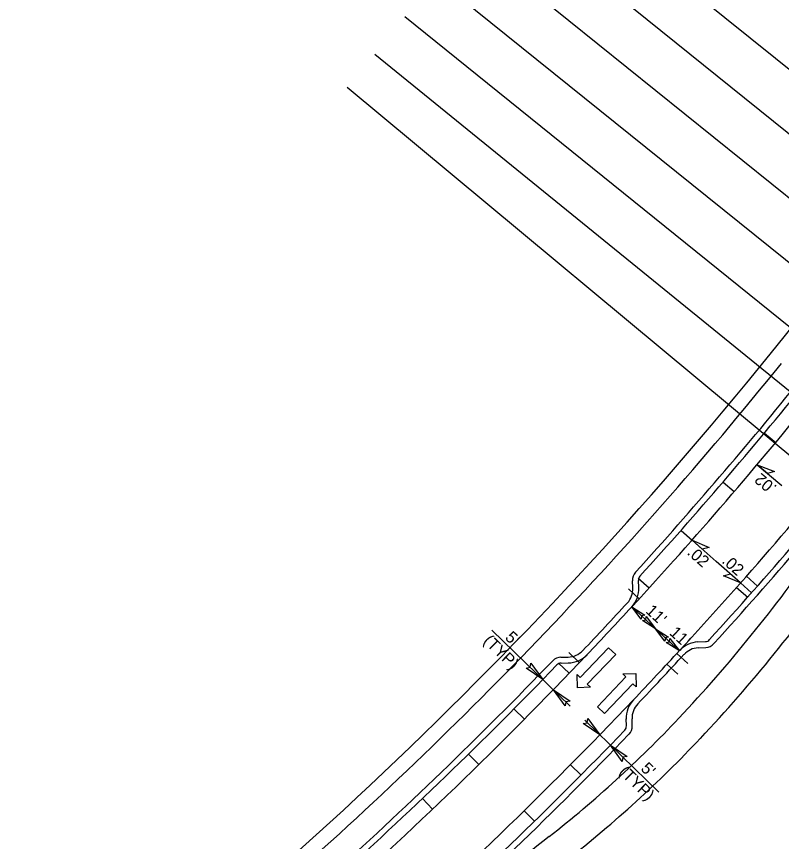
# Model space of a CAD drawing. Extents: x 1486489 to 1490134, y 497089 to 500876.
# Drawn here: x 1488292.7 to 1488552.5, y 498768.1 to 499048.4 of the extents above; entities that cross this region are included whole.
import ezdxf

# ---------------------------------------------------------------- set-up
doc = ezdxf.new("R2010")
doc.units = 0
for name, color, linetype in [('DEV PRELIMINARY STAMP CELL', 7, 'Continuous'), ('Gray Area Fill Shapes', 7, 'Continuous'), ('Prop Horizontal Alignment Station Label', 7, 'Continuous'), ('Scratch_Level_5', 7, 'Continuous'), ('Sheet Block Title CELL', 7, 'Continuous'), ('Sheet Border Standard 30in CELL', 7, 'Continuous'), ('Sheet Cutting Line CELL', 7, 'Continuous'), ('Sheet Plan CELL', 7, 'Continuous'), ('Sheet Plot Border Inside CELL', 7, 'Continuous'), ('Sheet Plot Border Outside CELL', 7, 'Continuous'), ('Sheet Sticker Exception Certification CELL', 7, 'Continuous'), ('Sheet Title CELL', 7, 'Continuous')]:
    doc.layers.add(name, color=color, linetype=linetype)

msp = doc.modelspace()

# ---------------------------------------------------------------- linework, layer by layer
at = {"layer": 'DEV PRELIMINARY STAMP CELL'}
for p, q in [((1488544.22, 498896.09), (1488552.63, 498889)), ((1488522.12, 498870.48), (1488530.36, 498863.19)), ((1488538.61, 498855.91), (1488530.36, 498863.19))]:
    msp.add_line(p, q, dxfattribs=at)
for points in [[(1488544.22, 498896.09), (1488550.1, 498893.75), (1488547.76, 498893.11)], [(1488522.12, 498870.48), (1488527.94, 498868.01), (1488525.58, 498867.42)], [(1488538.61, 498855.91), (1488532.79, 498858.38), (1488535.14, 498858.97)]]:
    msp.add_lwpolyline(points, close=True, dxfattribs=at)
at = {"layer": 'Prop Horizontal Alignment Station Label'}
msp.add_line((1488548.61, 498933.63), (1488574.78, 498966.09), dxfattribs=at)
for centre, radius, start, end in [((1487424.96, 499839.79), 1443.5, 305.25533, 321.11565), ((1487424.96, 499839.79), 1448.5, 311.19416, 321.11565), ((1488157.43, 499149.47), 495, 316.6966, 325.3537), ((1488157.43, 499149.47), 505, 316.6966, 325.3537), ((1488230.2, 499080.88), 395, 308.0345, 316.6966), ((1488230.2, 499080.88), 405, 308.0345, 316.6966), ((1488846.34, 498293.24), 605, 128.03451, 136.03603)]:
    msp.add_arc(centre, radius, start, end, dxfattribs=at)
at = {"layer": 'Scratch_Level_5'}
for p, q in [((1488502.01, 498854.22), (1488501.88, 498856.66)), ((1488524.19, 498833.88), (1488526.78, 498834.01)), ((1488477.61, 498830.71), (1488480.05, 498830.75)), ((1488501.83, 498807.41), (1488501.75, 498809.77))]:
    msp.add_line(p, q, dxfattribs=at)
for centre, radius, start, end in [((1487424.96, 499839.79), 1457, 317.71824, 321.11565), ((1487424.96, 499839.79), 1493, 317.71734, 321.11565), ((1488505.88, 498856.86), 4, 137.7182, 182.8519), ((1488495.01, 498853.87), 7, 317.3435, 2.8519), ((1487424.96, 499839.79), 1462, 316.47396, 317.34346), ((1488524.54, 498826.89), 7, 92.8495, 137.3496), ((1488526.58, 498838), 4, 272.8495, 317.7173), ((1488477.68, 498826.71), 4, 90.9656, 136.0992), ((1488479.93, 498837.75), 7, 270.9656, 316.474), ((1487424.96, 499839.79), 1488, 316.46337, 317.34959), ((1487424.96, 499839.79), 1457, 311.89155, 316.09919), ((1488508.74, 498810), 7, 136.4634, 181.939), ((1488497.83, 498807.27), 4, 316.0979, 1.939), ((1487424.96, 499839.79), 1493, 311.89155, 316.0979)]:
    msp.add_arc(centre, radius, start, end, dxfattribs=at)
at = {"layer": 'Sheet Block Title CELL'}
for p, q in [((1488546.69, 498906.83), (1488550.54, 498903.63)), ((1488532.65, 498890.2), (1488536.45, 498886.95)), ((1488518.37, 498873.79), (1488522.12, 498870.48)), ((1488542.35, 498852.6), (1488538.6, 498855.91)), ((1488461.61, 498813.12), (1488465.17, 498809.6)), ((1488446.19, 498797.77), (1488449.69, 498794.2)), ((1488480.8, 498794.12), (1488484.41, 498790.66)), ((1488430.53, 498782.66), (1488433.98, 498779.04)), ((1488465.08, 498778.49), (1488468.64, 498774.98))]:
    msp.add_line(p, q, dxfattribs=at)
for radius, start, end in [(1464, 317.34346, 321.11565), (1486, 317.34959, 321.11565), (1464, 311.51677, 316.47396), (1486, 311.51863, 316.46337)]:
    msp.add_arc((1487424.96, 499839.79), radius, start, end, dxfattribs=at)
at = {"layer": 'Sheet Border Standard 30in CELL'}
for p, q in [((1488503.84, 498857.59), (1488507.54, 498854.22)), ((1488540.6, 498858.18), (1488544.36, 498854.88)), ((1488540.6, 498858.18), (1488544.36, 498854.88)), ((1488500.5, 498853.94), (1488504.19, 498850.56)), ((1488537.27, 498854.4), (1488541.01, 498851.09)), ((1488480.23, 498832.27), (1488483.85, 498828.81)), ((1488517, 498831.99), (1488520.67, 498828.6)), ((1488476.81, 498828.7), (1488480.42, 498825.23)), ((1488513.58, 498828.29), (1488517.24, 498824.89))]:
    msp.add_line(p, q, dxfattribs=at)
at = {"layer": 'Sheet Cutting Line CELL'}
for p, q in [((1488509.72, 498840.32), (1488501.63, 498847.78)), ((1488454.16, 498839.93), (1488480.74, 498814.1)), ((1488517.81, 498832.87), (1488509.72, 498840.32)), ((1488485.71, 498809.26), (1488510.82, 498784.87))]:
    msp.add_line(p, q, dxfattribs=at)
at = {"layer": 'Sheet Plan CELL'}
for p, q in [((1488778.61, 498850.05), (1488467.24, 499101.15)), ((1488456.57, 499087.92), (1488767.94, 498836.82)), ((1488757.26, 498823.59), (1488445.9, 499074.69)), ((1488435.23, 499061.45), (1488746.59, 498810.35)), ((1488735.92, 498797.12), (1488424.55, 499048.22)), ((1488414.36, 499035.59), (1488724.76, 498783.3)), ((1488712.49, 498768.39), (1488405.02, 499024.24))]:
    msp.add_line(p, q, dxfattribs=at)
at = {"layer": 'Sheet Plot Border Inside CELL'}
for p, q in [((1488484.14, 498823.79), (1488493.8, 498833.93)), ((1488493.8, 498833.93), (1488496.19, 498831.65)), ((1488496.19, 498831.65), (1488486.53, 498821.52)), ((1488483.2, 498820.34), (1488483.05, 498824.83)), ((1488483.05, 498824.83), (1488484.14, 498823.79)), ((1488498.58, 498825.01), (1488503, 498825.15)), ((1488499.67, 498823.98), (1488498.58, 498825.01)), ((1488503, 498825.15), (1488503.14, 498820.67)), ((1488490.01, 498813.85), (1488499.67, 498823.98)), ((1488487.61, 498820.48), (1488483.2, 498820.34)), ((1488486.53, 498821.52), (1488487.61, 498820.48)), ((1488502.06, 498821.7), (1488492.4, 498811.57)), ((1488503.14, 498820.67), (1488502.06, 498821.7)), ((1488492.4, 498811.57), (1488490.01, 498813.85))]:
    msp.add_line(p, q, dxfattribs=at)
at = {"layer": 'Sheet Plot Border Outside CELL'}
for points in [[(1488504.83, 498843.61), (1488501.63, 498847.78), (1488506.08, 498844.93), (1488504.97, 498844.7)], [(1488506.52, 498844.48), (1488509.72, 498840.32), (1488505.27, 498843.17), (1488506.38, 498843.4)], [(1488512.92, 498836.16), (1488509.72, 498840.32), (1488514.17, 498837.47), (1488513.06, 498837.24)], [(1488514.61, 498837.03), (1488517.81, 498832.87), (1488513.36, 498835.72), (1488514.47, 498835.95)], [(1488467.41, 498828.68), (1488471.44, 498823.14), (1488465.74, 498827.01), (1488467.19, 498827.27)], [(1488479.06, 498814.12), (1488475.03, 498819.65), (1488480.73, 498815.79), (1488479.28, 498815.53)], [(1488486.77, 498809.85), (1488490.8, 498804.32), (1488485.09, 498808.19), (1488486.55, 498808.45)], [(1488498.42, 498795.3), (1488494.38, 498800.83), (1488500.09, 498796.96), (1488498.63, 498796.7)]]:
    msp.add_lwpolyline(points, close=True, dxfattribs=at)
at = {"layer": 'Sheet Sticker Exception Certification CELL'}
for p, q in [((1488504, 498854.32), (1488503.88, 498856.76)), ((1488524.09, 498835.88), (1488526.68, 498836.01)), ((1488477.64, 498828.71), (1488480.08, 498828.75)), ((1488499.83, 498807.34), (1488499.75, 498809.7))]:
    msp.add_line(p, q, dxfattribs=at)
for centre, radius, start, end in [((1487424.96, 499839.79), 1459, 317.71824, 321.11565), ((1487424.96, 499839.79), 1491, 317.71734, 321.11565), ((1488505.88, 498856.86), 2, 137.7182, 182.8519), ((1488495.01, 498853.87), 9, 317.3435, 2.8519), ((1487424.96, 499839.79), 1464, 316.47396, 317.34346), ((1488526.58, 498838), 2, 272.8495, 317.7173), ((1488524.54, 498826.89), 9, 92.8495, 137.3496), ((1488479.93, 498837.75), 9, 270.9656, 316.474), ((1487424.96, 499839.79), 1486, 316.46337, 317.34959), ((1487424.96, 499839.79), 1459, 311.89155, 316.09919), ((1488477.68, 498826.71), 2, 90.9656, 136.0992), ((1488508.74, 498810), 9, 136.4634, 181.939), ((1487424.96, 499839.79), 1491, 311.89078, 316.0979), ((1488497.83, 498807.27), 2, 316.0979, 1.939)]:
    msp.add_arc(centre, radius, start, end, dxfattribs=at)

# ---------------------------------------------------------------- texts
at = {"layer": 'Gray Area Fill Shapes'}
for rotation, p in [(139.8642, (1488551.21, 498888.69)), (318.5402, (1488520.18, 498865.87)), (318.5402, (1488531.98, 498862.99))]:
    msp.add_text('.02', height=4, rotation=rotation, dxfattribs=at).set_placement(p)
at = {"layer": 'Sheet Title CELL'}
for s, rotation, p in [("11'", 317.3435, (1488506.09, 498846.08)), ("5'", 315.8283, (1488458.37, 498837.08)), ("11'", 317.3435, (1488514.18, 498838.63)), ('(TYP)', 315.8283, (1488450.96, 498835.91)), ("5'", 315.8283, (1488504.44, 498792.56)), ('(TYP)', 315.8283, (1488497.03, 498791.39))]:
    msp.add_text(s, height=4, rotation=rotation, dxfattribs=at).set_placement(p)

doc.saveas('drawing.dxf')
